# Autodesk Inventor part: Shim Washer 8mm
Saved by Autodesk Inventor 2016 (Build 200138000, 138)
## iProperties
Created: 2015-11
Part Number: Shim Washer 8mm
Material: Generic
Document SubType Name: Modeling
Designer: John
Density: 1 g/cm^3
Appearance: Default
Author: John
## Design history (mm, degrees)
feature "SOLID1"
body "Solid1"
